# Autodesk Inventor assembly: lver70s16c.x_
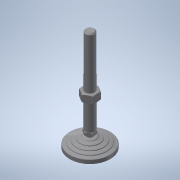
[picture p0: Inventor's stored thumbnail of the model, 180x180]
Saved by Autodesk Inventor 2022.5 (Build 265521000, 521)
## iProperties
Part Number: lver70s16c.x_
Material: 一般
Document SubType Name: Assembly
Designer: ImaoCorp
Sending System: SOLIDWORKS 2017-2017317
MC: AMD64
MC_MODEL: Intel64 Family 6 Model 60 Stepping 3, GenuineIntel
OS: Windows_NT
FRU: Parasolid Version 29.0, build 201,  4-17-2017
FORMAT: text
GUISE: transmit
KEY: lver70s16c
FILE: lver70s16c.x_t
DATE: Mon Jul 01 18:26:52 2019
Author: ImaoCorp
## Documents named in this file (3)
- X:\14_SW2022-Inv2022\00_全2023-1023新製品(TCC)まで\l\lver70s16c\LVER70S16C.iam
- X:\14_SW2022-Inv2022\00_全2023-1023新製品(TCC)まで\l\lver70s16c\lver70s16c_01.ipt
- X:\14_SW2022-Inv2022\00_全2023-1023新製品(TCC)まで\l\lver70s16c\lver70s16c_02.ipt
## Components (2 placed, 2 different names)
1. lver70s16c_01
2. lver70s16c_02
